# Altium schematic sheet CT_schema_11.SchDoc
size 146 x 119 mm
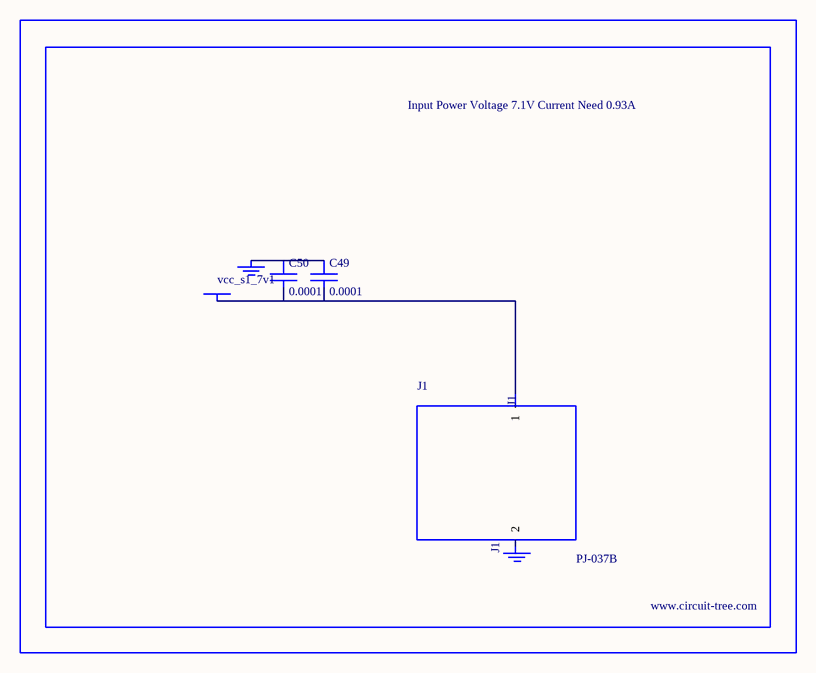
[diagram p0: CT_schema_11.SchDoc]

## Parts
BORDER10  (no value)
C49  0.0001  [EXV-9H]
C50  0.0001  [EXV-9H]
GND_INSTANCE_10_0  (no value)
GND_INSTANCE_10_1  (no value)
J1  PJ-037B  [PJ-037B_PACKAGE]
POWER_INSTANCE_10_0  vcc_s1_7v1

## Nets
NetC49_1: C49.1 C50.1 GND_INSTANCE_10_0.0(GND)
NetC49_2: C49.2 C50.2 J1.1 POWER_INSTANCE_10_0.0(PWR)

Not connected (* = marked no-connect by the designer): GND_INSTANCE_10_1 0(GND); J1 2

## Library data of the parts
BORDER10 = BORDER_PAGE10
C49 C50 = EDK107M035A9HAA
GND_INSTANCE_10_0 GND_INSTANCE_10_1 = GND
POWER_INSTANCE_10_0 = PWR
